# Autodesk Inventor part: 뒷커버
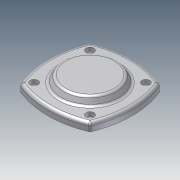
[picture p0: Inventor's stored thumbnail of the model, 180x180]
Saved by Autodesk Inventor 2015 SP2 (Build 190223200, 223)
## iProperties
Created: 2013-02
Part Number: 뒷커버
Document SubType Name: Modeling
Designer: 한국산업디자인학원[gmhk.co.kr]
Density: 1 g/cm^3
Material: 일반
Appearance: 기본값
Author: 한국산업디자인학원[gmhk.co.kr]
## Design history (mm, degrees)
sketch "스케치1"
  geometry: C1 r 30 at (0, 0) reference; A1 r 91.05 centre (0, -48.55) between (34.185, 35.839) and (-34.185, 35.839) reference; A2 r 91.05 centre (48.55, 0) between (-35.839, 34.185) and (-35.839, -34.185) reference; A3 r 3 centre (-33.058, 33.058) between (-34.185, 35.839) and (-35.839, 34.185) reference; A4 r 3 centre (33.058, 33.058) between (35.839, 34.185) and (34.185, 35.839) reference; A5 r 91.05 centre (-48.55, 0) between (35.839, -34.185) and (35.839, 34.185) reference; A6 r 3 centre (33.058, -33.058) between (34.185, -35.839) and (35.839, -34.185) reference; A7 r 91.05 centre (0, 48.55) between (-34.185, -35.839) and (34.185, -35.839) reference; A8 r 3 centre (-33.058, -33.058) between (-35.839, -34.185) and (-34.185, -35.839) reference; 1 further point
  node "참조1"
  node "참조2"
  node "참조3"
  node "참조4"
  node "참조5"
  node "참조6"
  node "참조7"
  node "참조8"
  node "참조9"
extrude "돌출1" new body sketch "스케치1" distance "d0" = 8; taper "d1" = 0 deg
sketch "스케치2"
  geometry: C1 r 30 at (0, 0); 1 further point
  constraints: 1 centre point, 1 coincident
  dimensions: "d2" = 60 diameter of C1
extrude "돌출2" join sketch "스케치2" distance "d3" = 7; taper "d4" = -30 deg
sketch "스케치3"
  geometry: C1 r 1.621 at (28.284, 28.284) reference; C2 r 1.621 at (-28.284, 28.284) reference; C3 r 1.621 at (-28.284, -28.284) reference; C4 r 1.621 at (28.284, -28.284) reference; 1 further point
hole "구멍2" sketch "스케치3" at (28.284, 28.284), (28.284, -28.284), (-28.284, -28.284), (-28.284, 28.284) diameter "d14" = 4.5; stored, may be unused: countersink angle "d18" = 90 deg, drill point angle "d20" = 118 deg; dims "d15" = 6, "d16" = 8, "d17" = 4.4, "d19" = 20
extrude "돌출3" join sketch "스케치1" distance "d21" = 12; taper "d22" = 0 deg
hole "구멍3" diameter "d25" = 30; stored, may be unused: countersink angle "d29" = 90 deg, drill point angle "d31" = 0 deg; dims "d23" = 10, "d24" = 10, "d26" = 6, "d27" = 40, "d28" = 12, "d30" = 15
fillet "모깎기1" dims "d32" = 3, "d33" = 0.3
chamfer "모따기1" distance "d34" = 1; stored, may be unused: second distance "d35" = 2, angle "d36" = 45 deg
node "솔리드1"
node "참조10"
node "참조11"
node "참조12"
node "참조13"
